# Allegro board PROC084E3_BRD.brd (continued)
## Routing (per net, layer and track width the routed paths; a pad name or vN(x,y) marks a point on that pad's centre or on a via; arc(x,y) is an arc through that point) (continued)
PRG1_RGMII1_RD3_R: length 6.3
  BOTTOM w0.173: R197.2 63.47,68.41 62.87,69.01 62.87,69.57 61.46,70.98 61.46,72.84 61.23,73.08 U30.36
PRG1_RGMII1_REF_CLK: length 30.8
  TOP w0.173: v1(57.15,83.11) 57.15,81.83 60.58,78.4 65.53,78.4 75.87,68.06 v1(78.51,68.06)
  BOTTOM w0.173: v1(57.15,83.11) 57.15,81.6 R186.1 ; R208.2 v1(78.51,68.06)
PRG1_RGMII1_RESET#: length 21.3
  TOP w0.173: v1(52.66,62.06) 53.69,63.08 58.94,63.08 60.53,64.67 60.53,69.86 59.97,70.42 56.97,70.42 v1(56.66,70.73)
  BOTTOM w0.173: U33.4 v1(52.66,62.06) ; U30.43 57.16,71.23 v1(56.66,70.73)
PRG1_RGMII1_RX_CTL: length 64.6
  L06_SIG2 w0.102: v1(71.91,118.84) 72.8,118.84 73.74,117.9 73.74,116.39 75.38,114.76 75.38,106.39 74.32,105.33 74.32,85.1 67.47,78.25 67.47,77.69 67.47,77.14 66.07,75.74 66.07,75.35 64.44,73.73 v1(64.44,66.93)
  BOTTOM w0.173: R342.2 v1(71.91,118.84) ; v1(64.44,66.93) 63.44,65.93 60.79,65.93 60.56,66.16 R200.1
PRG1_RGMII1_RX_CTL_R: length 7.8
  BOTTOM w0.173: U30.38 59.66,71.15 60.99,69.83 R47.1 59.58,69.22 R201.2 60.15,68.63 60.15,67.52 59.76,67.14 R200.2
PRG1_RGMII1_RXC: length 64.8
  L06_SIG2 w0.102: v1(66.52,75.44) 66.93,75.44 67.7,76.21 67.7,77.78 67.7,78.16 74.93,85.39 74.93,92.78 75.66,93.51 75.66,94.59 75.56,94.7 74.91,94.7 74.81,94.8 74.81,95.2 74.91,95.31 75.56,95.31 75.66,95.41 75.66,95.81 75.56,95.91 74.91,95.91 74.81,96.02 74.81,96.42 74.91,96.52 75.56,96.52 75.66,96.63 75.66,97.35 75.56,97.45 74.91,97.45 74.76,97.59 74.76,97.92 74.91,98.06 75.56,98.06 75.66,98.16 75.66,98.57 75.56,98.67 74.91,98.67 74.81,98.77 74.81,99.18 74.91,99.28 75.56,99.28 75.66,99.38 75.66,99.79 75.56,99.89 74.91,99.89 74.81,99.99 74.81,100.4 74.91,100.5 75.56,100.5 75.66,100.6 75.66,101 75.56,101.11 74.91,101.11 74.81,101.21 74.81,101.61 74.91,101.72 75.56,101.72 75.66,101.82 75.66,102.22 75.56,102.33 74.91,102.33 74.81,102.43 74.81,102.83 74.91,102.94 75.56,102.94 75.66,103.04 75.66,103.44 75.56,103.54 74.91,103.54 74.81,103.65 74.81,104.05 74.91,104.15 75.56,104.15 75.66,104.26 75.66,104.66 75.56,104.76 74.91,104.76 74.81,104.87 74.81,105.27 74.91,105.37 75.56,105.37 75.66,105.48 75.66,115 74.21,116.45 74.21,118.28 74.31,118.38 74.69,118.38 74.89,118.18 v1(74.89,116.76)
  BOTTOM w0.173: v1(74.89,116.76) R343.2 ; R191.1 v1(66.52,75.44)
PRG1_RGMII1_RXC_R: length 4.9
  BOTTOM w0.173: R191.2 65.04,74.86 61.62,74.86 61.4,75.08 U30.32
PRG1_RGMII1_TD0: length 49.2
  L06_SIG2 w0.102: v1(71.95,116.29) 73.35,116.29 74.27,115.36 74.27,111.55 73.94,111.21 73.94,110.62 73.24,109.92 71.13,109.92 69.72,108.51 69.72,92.4 69.82,92.3 70.61,92.3 70.71,92.2 70.71,91.79 70.61,91.69 69.82,91.69 69.72,91.59 69.72,91.18 69.82,91.08 70.61,91.08 70.71,90.98 70.71,90.58 70.61,90.47 69.82,90.47 69.72,90.37 69.72,83.12 65.62,79.01 v1(65.28,79.01)
  BOTTOM w0.173: R189.1 v1(65.28,79.01) ; R344.2 v1(71.95,116.29)
PRG1_RGMII1_TD0_R: length 3.7
  BOTTOM w0.173: R189.2 62.94,78.43 62.94,77.94 62.08,77.08 U30.28
PRG1_RGMII1_TD1: length 49.2
  L06_SIG2 w0.102: v1(73.75,114.55) 74.03,114.27 74.03,112.63 73.33,111.93 69.68,111.93 68.83,111.08 68.83,85.94 68.72,85.83 68,85.83 67.9,85.93 67.9,88.52 67.8,88.62 67.16,88.62 67.06,88.52 67.06,81.45 65.76,80.15 v1(65.28,80.15)
  BOTTOM w0.173: v1(73.75,114.55) 74.67,114.55 74.88,114.77 R345.2 ; R188.1 v1(65.28,80.15)
PRG1_RGMII1_TD1_R: length 4.3
  BOTTOM w0.173: U30.27 62.04,77.58 62.6,78.13 62.6,79.23 R188.2
PRG1_RGMII1_TD2: length 49.4
  L06_SIG2 w0.102: v1(65.28,81.29) 65.4,81.29 65.94,81.83 65.94,87.46 65.61,87.79 64.51,87.79 64.11,88.19 64.11,91.59 64.27,91.76 64.83,91.76 65,91.59 65,89.42 65.12,89.3 65.74,89.3 65.94,89.49 65.94,91.49 66.11,91.66 66.7,91.66 66.87,91.49 66.87,90.37 67.18,90.06 68.29,90.06 68.61,90.37 68.61,111.65 70.38,113.43 v1(71.92,113.43)
  BOTTOM w0.173: R346.2 72.74,113.43 v1(71.92,113.43) ; R187.1 v1(65.28,81.29)
PRG1_RGMII1_TD2_R: length 4.9
  BOTTOM w0.173: U30.26 61.86,78.08 62.25,78.46 62.25,80.03 R187.2
PRG1_RGMII1_TD3: length 49.1
  L06_SIG2 w0.102: v1(65.28,82.44) 64.8,81.96 64.8,79.99 65.09,79.69 65.65,79.69 67.54,81.58 67.54,85.35 67.65,85.45 68.24,85.45 68.35,85.35 68.35,83.09 68.47,82.96 68.88,82.96 69.06,83.15 69.06,110.92 69.81,111.67 v1(73.71,111.67)
  BOTTOM w0.173: R347.2 74.6,112.19 74.07,111.67 v1(73.71,111.67) ; R183.1 v1(65.28,82.44)
PRG1_RGMII1_TD3_R: length 5.3
  BOTTOM w0.173: U30.25 61.49,78.58 61.9,78.99 61.9,80.82 R183.2
PRG1_RGMII1_TX_CTL: length 49.4
  L06_SIG2 w0.102: v1(62.18,67.54) 63.09,68.45 63.09,77.48 65.07,79.47 65.75,79.47 69.49,83.21 69.49,108.86 71.14,110.5 v1(72.13,110.5)
  BOTTOM w0.173: v1(72.13,110.5) 72.74,110.5 R348.2 ; R199.1 62.18,68.19 v1(62.18,67.54)
PRG1_RGMII1_TX_CTL_R: length 3.9
  BOTTOM w0.173: R199.2 62.13,69.63 60.16,71.59 U30.37
PRG1_RGMII1_TXC: length 49.3
  L06_SIG2 w0.102: v1(65.28,77.87) 65.66,78.25 65.66,78.73 71.6,84.67 71.6,85.51 71.5,85.61 70.37,85.61 70.27,85.71 70.27,86.12 70.37,86.22 71.5,86.22 71.6,86.32 71.6,86.73 71.5,86.83 70.37,86.83 70.27,86.93 70.27,87.34 70.37,87.44 71.5,87.44 71.6,87.54 71.6,87.95 71.5,88.05 70.37,88.05 70.27,88.15 70.27,88.55 70.37,88.66 71.5,88.66 71.6,88.76 71.6,89.16 71.5,89.27 70.37,89.27 70.27,89.37 70.27,89.77 70.37,89.88 71.5,89.88 71.6,89.98 71.6,91.94 69.95,93.59 69.95,107.52 71.13,108.7 73.86,108.7 v1(73.86,108.69)
  BOTTOM w0.173: R190.1 v1(65.28,77.87) ; v1(73.86,108.69) 74.14,108.97 74.15,108.97 74.4,109.22 R349.2
PRG1_RGMII1_TXC_R: length 3.1
  BOTTOM w0.173: R190.2 62.3,76.65 60.98,76.65 U30.29
PRG1_RGMII1_XIN: length 2.3
  BOTTOM w0.173: U30.15 55.66,81.1 R184.2
PRG1_RGMII1_XOUT: length 2.2
  BOTTOM w0.173: R185.2 55.16,81.14 U30.14
PRG1_RGMII2_100MBPS: length 18.5
  TOP w0.132: J20.B13 9.84,74.69 8.42,74.69
  TOP w0.173: Q4.3 10.41,67.05 R49.2 10.14,67.72 9.55,68.32 7.14,68.32 4.95,70.5 4.95,74.11 5.53,74.69 8.42,74.69
PRG1_RGMII2_1000MBPS: length 10.7
  TOP w0.173: J20.B14 10.9,73.67 16.82,67.75 16.82,67.7 17.2,67.32 R51.2 17.53,67.05 Q6.3
PRG1_RGMII2_ACT_LED: length 9.4
  TOP w0.173: J20.B11 10.85,80.08 12.45,81.68 12.45,84.42 14.86,86.83 Q2.3
PRG1_RGMII2_CLK_OUT: length 7.7
  TOP w0.173: U3.18 v1(38.62,86.51)
  BOTTOM w0.173: TP11.1 35.82,83.71 v1(38.62,86.51)
PRG1_RGMII2_D0_N: length 32.4
  TOP w0.102: J20.B2 13.84,78.88 13.84,79.82 14.15,80.13 14.15,81.99 15.18,83.02 22.75,83.02 24.3,84.57 24.3,91 24.84,91.54 34.6,91.54 34.72,91.43 U3.2
PRG1_RGMII2_D0_P: length 32.5
  TOP w0.102: J20.B1 13.67,80.02 13.88,80.24 13.88,82.1 15.07,83.29 22.64,83.29 24.03,84.68 24.03,91.11 24.73,91.81 34.6,91.81 34.72,91.93 U3.1
PRG1_RGMII2_D1_N: length 28.8
  TOP w0.102: U3.5 34.72,89.93 34.6,90.04 26.14,90.04 25.59,89.49 25.59,83.69 24.27,82.37 17.23,82.37 16.69,81.83 16.69,80.15 16.41,79.87 16.41,78.85 J20.B4
PRG1_RGMII2_D1_P: length 28.8
  TOP w0.102: J20.B3 16.18,80.02 16.42,80.26 16.42,81.94 17.12,82.64 24.16,82.64 25.32,83.8 25.32,89.6 26.03,90.31 34.6,90.31 34.72,90.43 U3.4
PRG1_RGMII2_D2_N: length 25.2
  TOP w0.102: J20.B6 18.95,78.85 18.95,79.87 19.23,80.15 19.23,81.29 19.65,81.71 26.47,81.71 27.41,82.66 27.41,88.23 27.72,88.54 34.6,88.54 34.72,88.43 U3.8
PRG1_RGMII2_D2_P: length 25.2
  TOP w0.102: U3.7 34.72,88.93 34.6,88.81 27.61,88.81 27.14,88.35 27.14,82.77 26.36,81.98 19.54,81.98 18.96,81.4 18.96,80.26 18.72,80.02 J20.B5
PRG1_RGMII2_D3_N: length 21.2
  TOP w0.102: J20.B8 21.49,78.85 21.49,79.87 21.77,80.15 21.77,80.87 21.99,81.09 29.11,81.09 29.75,81.73 29.75,86.41 30.38,87.04 34.6,87.04 34.72,86.93 U3.11
PRG1_RGMII2_D3_P: length 21.3
  TOP w0.102: J20.B7 21.26,80.02 21.5,80.26 21.5,80.98 21.88,81.36 29,81.36 29.48,81.84 29.48,86.52 30.27,87.31 34.6,87.31 34.72,87.43 U3.10
PRG1_RGMII2_GPIO0_100: length 61.7
  TOP w0.173: R14.2 v1(39.88,95.09) 40.78,94.19 40.78,93.29 40.62,93.13 U3.39 ; Q4.1 v1(9.46,64.42)
  L03_SIG1 w0.102: v1(39.88,95.09) 39.37,94.58 38.46,94.58 38.31,94.73 37.93,94.73 36.58,93.38 36.58,73.1 27.09,63.62 16.61,63.62 14.86,65.37 10.41,65.37 v1(9.46,64.42)
  BOTTOM w0.173: v1(39.88,95.09) R14.2
PRG1_RGMII2_GPIO1: length 4.9
  TOP w0.173: R13.2 v1(38.73,95.09) 39.16,95.09 40.4,93.85 40.4,93.44 40.12,93.16 U3.40
  BOTTOM w0.173: v1(38.73,95.09) R13.2
PRG1_RGMII2_LED0: length 4.4
  TOP w0.173: R10.2 v1(35.31,95.09) 36.62,93.77 U3.47
  BOTTOM w0.173: v1(35.31,95.09) R10.2
PRG1_RGMII2_LED1_1000: length 49.9
  TOP w0.173: U3.46 37.12,94.41 v1(36.45,95.09) R11.2 ; Q6.1 v1(16.58,64.42)
  L03_SIG1 w0.102: v1(36.45,95.09) 36.35,94.99 36.35,74.61 25.68,63.95 17.05,63.95 v1(16.58,64.42)
  BOTTOM w0.173: v1(36.45,95.09) R11.2
PRG1_RGMII2_LED2_ACT: length 28.7
  TOP w0.173: U3.45 37.59,92.71 v1(37.59,95.09) R12.2 ; Q2.1 v1(15.81,90.73)
  L03_SIG1 w0.102: v1(37.59,95.09) 37.11,95.57 35,95.57 31.14,91.71 16.79,91.71 v1(15.81,90.73)
  BOTTOM w0.173: v1(37.59,95.09) R12.2
PRG1_RGMII2_RBIAS: length 2.3
  TOP w0.173: U3.12 v1(34.29,86.43)
  BOTTOM w0.173: R182.2 34.9,86.52 34.81,86.43 v1(34.29,86.43)
PRG1_RGMII2_RD0: length 64.9
  TOP w0.173: J1.39 v1(83.77,102.01) ; v1(48.65,91.69) 48.52,91.69 48.49,91.72 R24.1
  L03_SIG1 w0.102: v1(48.65,91.69) 48.05,91.69 47.81,91.45 47.81,90.64 49.77,88.67 58.63,88.67 59.81,87.48 60.08,87.48 60.18,87.59 60.18,88.69 60.28,88.79 60.69,88.79 60.79,88.69 60.79,87.59 60.89,87.48 61.3,87.48 61.4,87.59 61.4,88.69 61.5,88.79 61.84,88.79 61.94,88.69 61.94,87.6 62.05,87.48 71.25,87.48 76.25,92.48 76.25,95.7 76.35,95.8 76.63,95.8 76.73,95.7 76.73,91.94 76.83,91.83 77.06,91.83 77.22,91.99 77.22,100.78 77.49,101.05 78.88,101.05 79.15,100.78 81.49,100.78 81.83,101.12 83.36,101.12 83.51,101.27 83.51,101.49 83.77,101.75 v1(83.77,102.01)
PRG1_RGMII2_RD0_R: length 6.4
  TOP w0.173: R24.2 46.71,91.45 45.56,91.45 R180.2 44.98,91.99 44.97,91.99 R181.1 44.77,90.49 42.44,90.49 U3.33
PRG1_RGMII2_RD1: length 64.9
  TOP w0.173: R23.1 46.28,93.17 46.51,93.4 47.33,93.4 v1(47.88,92.85) ; J1.43 v1(84.01,103.01)
  L03_SIG1 w0.102: v1(47.88,92.85) 48.14,92.85 49.11,91.88 49.11,90.77 50.73,89.15 62.65,89.15 63.99,87.81 64.38,87.81 64.48,87.91 64.48,88.81 64.58,88.91 64.99,88.91 65.09,88.81 65.09,87.91 65.19,87.81 65.6,87.81 65.7,87.91 65.7,88.81 65.8,88.91 66.21,88.91 66.31,88.81 66.31,87.91 66.41,87.81 66.82,87.81 66.92,87.91 66.92,88.81 67.02,88.91 67.43,88.91 67.53,88.81 67.53,87.91 67.63,87.81 70.28,87.81 75.87,93.4 75.87,99.18 75.97,99.28 76.25,99.28 76.35,99.18 76.35,96.31 76.45,96.2 76.73,96.2 76.83,96.31 76.83,100.87 77.46,101.49 78.88,101.49 79.48,102.09 82.12,102.09 82.29,101.92 82.66,101.92 82.93,102.19 82.93,102.3 83.64,103.01 v1(84.01,103.01)
PRG1_RGMII2_RD1_R: length 4.4
  TOP w0.173: U3.34 43.86,90.93 44.26,91.32 44.26,92.8 44.63,93.17 R23.2
PRG1_RGMII2_RD2: length 64.7
  TOP w0.173: J1.41 83.16,102.51 83.06,102.41 82.51,102.41 82.48,102.38 v1(82.48,102.38) ; R22.1 48.46,94.57 v1(47.88,93.99)
  L03_SIG1 w0.102: v1(47.88,93.99) 48.79,93.99 49.47,93.31 49.47,91.45 51.34,89.58 61.81,89.58 61.91,89.68 61.91,91.07 62.01,91.18 62.42,91.18 62.52,91.07 62.52,89.68 62.62,89.58 63.03,89.58 63.13,89.68 63.13,91.07 63.23,91.18 63.64,91.18 63.74,91.07 63.74,89.68 63.84,89.58 65.74,89.58 66.95,90.79 69.36,90.79 69.46,90.69 69.46,89.79 69.56,89.69 69.84,89.69 69.94,89.79 69.94,90.69 70.04,90.79 72.94,90.79 74.63,92.47 74.63,95.85 74.73,95.95 75.01,95.95 75.11,95.85 75.11,93.56 75.21,93.45 75.49,93.45 75.59,93.56 75.59,101.35 76.64,102.41 78.05,102.41 78.37,102.09 78.75,102.09 79.06,102.41 82.45,102.41 v1(82.48,102.38)
PRG1_RGMII2_RD2_R: length 9.2
  TOP w0.173: U3.35 43.44,91.43 43.68,91.67 43.68,93.57 44.43,94.32 R179.2 44.98,95.68 ; R22.2 47.11,95.15 46.38,95.15 46.33,95.1 45.56,95.1 45.51,95.15 45.5,95.15 44.98,95.68 ; R178.1 44.98,95.68
PRG1_RGMII2_RD3: length 65.3
  TOP w0.173: R19.1 45.97,96.93 46.68,96.22 v1(46.68,95.65) ; J1.45 83.36,103.51 v1(82.86,103.01)
  L03_SIG1 w0.102: v1(46.68,95.65) 46.95,95.38 46.95,95.38 47.07,95.26 54.49,95.26 54.59,95.16 54.59,93.09 54.69,92.99 55.1,92.99 55.2,93.09 55.2,95.16 55.3,95.26 55.71,95.26 55.81,95.16 55.81,93.09 55.91,92.99 56.32,92.99 56.42,93.09 56.42,95.16 56.52,95.26 63.55,95.26 67.64,91.18 73,91.18 74.35,92.52 74.35,97.8 74.45,97.9 74.73,97.9 74.83,97.8 74.83,96.48 74.93,96.38 75.21,96.38 75.31,96.48 75.31,98.28 75.21,98.39 74.73,98.39 74.63,98.49 74.63,101.88 75.75,103.01 v1(82.86,103.01)
PRG1_RGMII2_RD3_R: length 6.4
  TOP w0.173: R19.2 44.99,97.06 44.56,96.63 44.56,96.54 44.4,96.38 44.4,95.27 43.12,93.99 43.12,92.36 42.69,91.93 U3.36
PRG1_RGMII2_REF_CLK: length 38.5
  TOP w0.173: R32.1 39.34,82.67 44.15,82.67 44.35,82.46 44.35,82.13 44.7,81.78 56.46,81.78 60.64,77.6 62.46,77.6 64.4,75.65 64.4,72.07 66.33,70.14 v1(66.33,68.11)
  BOTTOM w0.173: R207.2 v1(66.33,68.11)
PRG1_RGMII2_RESET#: length 12.9
  TOP w0.173: U3.43 38.62,93.77 v1(38.12,94.27) ; U2.4 v1(29.52,97.69)
  BOTTOM w0.173: v1(38.12,94.27) 35.15,94.27 31.74,97.69 v1(29.52,97.69)
PRG1_RGMII2_RX_CTL: length 64.9
  TOP w0.173: J1.47 83.36,104.01 v1(83.36,104.01) ; R16.1 v1(41.91,98.65)
  L03_SIG1 w0.102: v1(83.36,104.01) 83.35,104.02 83.35,104.03 82.86,104.51 73.92,104.51 73.1,103.69 73.1,92.71 72.91,92.52 68.53,92.52 63.59,97.46 50.69,97.46 45.96,102.19 41.7,102.19 40.65,101.14 40.65,99.16 41.16,98.65 v1(41.91,98.65)
PRG1_RGMII2_RX_CTL_R: length 7.6
  TOP w0.173: U3.38 41.12,94.08 42.45,95.41 R170.1 41.03,95.8 R15.2 41.11,95.79 41.6,96.28 41.6,97.16 41.09,97.67 R16.2
PRG1_RGMII2_RXC: length 60.1
  TOP w0.173: v1(47.51,89.39) 48,89.88 R25.1 ; v1(82.62,104.04) 83.09,104.51 J1.49
  L03_SIG1 w0.102: v1(47.51,89.39) 47.51,89.79 46.08,91.23 46.08,95.92 46.34,96.19 48.19,96.19 48.83,95.54 63.88,95.54 68.02,91.4 72.91,91.4 73.89,92.38 73.89,101.47 76.43,104.01 82.59,104.01 v1(82.62,104.04)
PRG1_RGMII2_RXC_R: length 4.8
  TOP w0.173: R25.2 46.53,90.29 46.34,90.11 43.52,90.11 43.49,90.14 43.08,90.14 42.86,89.93 U3.32
PRG1_RGMII2_TD0: length 72.1
  TOP w0.173: J1.14 93.08,95.51 v1(93.58,95.01) ; R29.1 v1(46.74,85.99)
  L03_SIG1 w0.102: v1(46.74,85.99) 47.32,85.99 47.5,85.82 47.5,84.02 47.6,83.91 52.35,83.91 52.53,83.73 52.53,83.46 52.35,83.28 47.35,83.28 47.24,83.17 47.24,82.9 47.35,82.79 55,82.79 57.08,84.88 62.26,84.88 63.25,85.87 72.45,85.87 79.79,93.2 80.19,93.6 80.19,95.33 80.46,95.6 82.56,97.7 88.87,97.7 92.03,94.55 93.12,94.55 v1(93.58,95.01)
PRG1_RGMII2_TD0_R: length 3.7
  TOP w0.173: R29.2 44.4,86.57 44.4,87.06 43.53,87.93 U3.28
PRG1_RGMII2_TD1: length 72
  TOP w0.173: J1.18 93.08,96.51 v1(93.58,96.01) ; R30.1 v1(46.74,84.85)
  L03_SIG1 w0.102: v1(46.74,84.85) 46.18,84.85 45.75,85.29 45.75,87.72 45.85,87.82 59.05,87.82 59.16,87.72 59.16,87.44 59.05,87.34 54.43,87.34 54.33,87.24 54.33,86.96 54.43,86.86 72.48,86.86 79.5,93.88 79.5,95.72 82.27,98.49 90.27,98.49 92.23,96.53 93.05,96.53 v1(93.58,96.01)
PRG1_RGMII2_TD1_R: length 4.3
  TOP w0.173: U3.27 43.5,87.43 44.05,86.87 44.05,85.77 R30.2
PRG1_RGMII2_TD2: length 72.6
  TOP w0.173: R31.1 v1(46.74,83.71) ; J1.16 v1(92.43,96.01)
  L03_SIG1 w0.102: v1(92.43,96.01) 90.18,98.26 82.37,98.26 79.73,95.63 79.73,93.79 79.6,93.66 72.52,86.58 48.63,86.58 48.46,86.75 48.46,86.89 48.63,87.06 53.59,87.06 53.7,87.16 53.7,87.44 53.54,87.59 46.33,87.59 46.05,87.31 46.05,86.02 46.71,85.36 47.02,85.36 47.19,85.18 47.19,84.63 46.92,84.36 45.96,84.36 45.82,84.22 45.82,83.81 45.93,83.71 v1(46.74,83.71)
PRG1_RGMII2_TD2_R: length 4.9
  TOP w0.173: U3.26 43.32,86.93 43.71,86.54 43.71,84.98 R31.2
PRG1_RGMII2_TD3: length 72.3
  TOP w0.173: J1.10 92.92,94.51 v1(93.58,93.85) ; R35.1 v1(46.74,82.56)
  L03_SIG1 w0.102: v1(93.58,93.85) 93.31,94.12 93.31,94.15 93.13,94.32 91.55,94.32 88.39,97.47 82.65,97.47 80.55,95.37 80.42,95.24 80.42,93.51 79.88,92.97 72.52,85.61 65.11,85.61 65.01,85.51 65.01,85.23 65.11,85.13 71.47,85.13 71.57,85.03 71.57,84.75 71.47,84.65 57.18,84.65 55.09,82.56 v1(46.74,82.56)
PRG1_RGMII2_TD3_R: length 5.3
  TOP w0.173: U3.25 42.95,86.43 43.36,86.01 43.36,84.18 R35.2
PRG1_RGMII2_TX_CTL: length 72.7
  TOP w0.173: v1(44.18,97.44) 43.81,97.44 43.59,97.22 R17.1 ; v1(92.43,93.85) 92.43,93.88 92.31,94.01 J1.8
  L03_SIG1 w0.102: v1(92.43,93.85) 91.22,93.85 88.54,96.53 82.04,96.53 80.64,95.14 80.64,93.41 79.98,92.74 71.65,84.42 57.43,84.42 55.09,82.08 46.57,82.08 45.24,83.41 45.24,95.53 44.91,95.86 44.91,96.71 v1(44.18,97.44)
PRG1_RGMII2_TX_CTL_R: length 4
  TOP w0.173: R17.2 43.55,95.8 41.62,93.87 U3.37
PRG1_RGMII2_TXC: length 72.3
  TOP w0.173: R28.1 v1(46.74,87.14) ; J1.12 v1(92.43,95.01)
  L03_SIG1 w0.102: v1(92.43,95.01) 89.41,98.03 82.46,98.03 79.96,95.53 79.96,93.69 79.69,93.43 72.44,86.17 63.17,86.17 62.48,85.49 49.07,85.49 48.97,85.38 48.97,85.1 49.07,85 56.22,85 56.33,84.9 56.33,84.65 56.22,84.55 48.16,84.55 48.01,84.7 48.01,85.87 v1(46.74,87.14)
PRG1_RGMII2_TXC_R: length 3.1
  TOP w0.173: R28.2 43.76,88.36 42.44,88.36 U3.29
PRG1_RGMII2_XIN: length 2.3
  TOP w0.173: R32.2 37.12,83.91 U3.15
PRG1_RGMII2_XOUT: length 2.2
  TOP w0.173: R33.2 36.62,83.86 U3.14
PRG1_RGMII_INT#: length 116.7
  TOP w0.173: v1(76.53,44.49) 80.09,44.49 82.73,47.13 J2.17 ; R41.1 56.2,70.96 56.66,71.43 v1(56.66,71.49) 57.32,70.84 61.99,70.84 65.41,67.43 75.71,67.43 v1(80.74,62.4) ; U3.44 v1(38.12,93.51)
  L03_SIG1 w0.102: v1(56.66,71.49) 54.76,71.49 52.25,68.98 52.25,66.48 51.13,65.37 50.9,65.37 50.26,64.73 50.26,61.89 47.81,59.44 46.55,59.44 45.31,60.68 45.31,62.47 36.88,70.91 36.88,86.02 38.12,87.26 v1(38.12,93.51)
  L06_SIG2 w0.102: v1(80.74,62.4) 80.06,61.72 80.06,49.06 76.53,45.53 v1(76.53,44.49)
  BOTTOM w0.173: U30.44 v1(56.66,71.49)
PRG1_UART0_CTSN: length 97.4
  TOP w0.173: R285.1 v1(98.3,102.05)
  L03_SIG1 w0.102: v1(67.99,179.36) 67.99,177.16 86.74,158.41 86.74,132.37 98.3,120.82 v1(98.3,102.05)
  BOTTOM w0.173: R284.1 v1(67.99,179.36)
PROFI_D1: length 8
  BOTTOM w0.173: T1.4 32.77,116.49 32.94,116.31 32.94,112.56 31.68,111.3 U26.1
PROFI_D2: length 21.9
  BOTTOM w0.173: T1.1 31.49,123.72 31.66,123.89 35.01,123.89 35.36,123.54 35.36,112.69 32.7,110.03 U26.2
PROFI_DE/RE#: length 5.5
  BOTTOM w0.173: U26.6 R162.2 R163.1 U26.7
PROFI_EN#: length 2
  TOP w0.173: U1.4 19.3,112.29 R5.1
PROFI_PG: length 3.5
  TOP w0.173: v1(16.75,111.38) R4.1 16.76,112.16 U1.2
  BOTTOM w0.173: R4.1 v1(16.75,111.38)
PROFI_UART0_RTSN: length 25.8
  L06_SIG2 w0.102: v1(48.96,118.07) 49.45,117.58 49.45,115.2 45.8,111.55 39.07,111.55 34.01,106.49 34.01,105.44 v1(34.5,104.95)
  BOTTOM w0.173: R162.1 v1(34.5,104.95) ; U22.4 v1(48.96,118.07)
PROFI_UART0_RXD: length 22.5
  L06_SIG2 w0.102: v1(49.98,115.47) 49.98,115.41 41.24,106.67 34.95,106.67 v1(34.5,106.22)
  BOTTOM w0.173: v1(49.98,115.47) 49.33,116.12 U22.7 ; R161.1 v1(34.5,106.22)
PROFI_UART0_TXD: length 21.2
  L06_SIG2 w0.102: v1(34.5,102.41) 34.05,102.41 33.77,102.69 33.77,112.04 37.85,116.12 v1(39.94,116.12)
  BOTTOM w0.173: v1(39.94,116.12) 40.59,115.47 U22.9 ; R165.1 v1(34.5,102.41)
PROFI_UART_RX: length 2.1
  BOTTOM w0.173: U26.5 R161.2
PROFI_UART_SEL: length 146.7
  TOP w0.173: v1(65.02,119.34) 64.44,119.93 50.54,119.93 v1(49.98,119.37) ; U42.1 69.67,41.69 69.38,41.99 67,41.99 v1(64.55,44.43)
  L03_SIG1 w0.102: v1(78.43,66.39) 78.22,66.6 68.61,66.6 64.41,62.41 64.41,44.58 v1(64.55,44.43)
  L06_SIG2 w0.102: v1(65.02,119.34) 65.02,123.2 66.74,124.92 74.7,124.92 79.46,120.16 79.46,116.58 78.4,115.53 78.4,112.29 v1(81.82,108.88)
  BOTTOM w0.173: v1(65.02,119.34) 64.37,119.99 U23.1 60.82,119.99 60.56,120.25 R154.1 ; U22.1 49.33,120.02 v1(49.98,119.37) ; v1(78.43,66.39) 78.61,66.39 79.72,67.5 79.72,74.47 80.43,75.19 80.43,96.88 81.15,97.59 81.15,103.96 82.16,104.98 82.16,108.7 81.99,108.88 v1(81.82,108.88) 81.35,108.88 79.73,110.5 R300.2
PROFI_UART_TX: length 2.1
  BOTTOM w0.173: U26.8 R165.2
PROFIB_GND: length 10.7
  TOP w0.254: v1(17.6,111.42) 18.18,112 R5.2 18.03,112.29 U1.3 ; C8.1 v1(9.09,116.86)
  BOTTOM w0.254: U26.9 v1(20.03,102.41) ; U26.14 v1(20.03,108.76) ; C113.2 19.92,110.14 v1(20.03,110.03) U26.15 ; U26.11 v1(20.03,104.95)
  vias: v1(17.45,124.96) v1(18.64,124.94) v1(18.67,100.4) v1(19.91,100.4) v1(20.14,124.91) v1(21.16,100.4) v1(21.37,125.81) v1(21.36,124.94)
PROFIBUS_DATA_N: length 18
  BOTTOM w0.102: 16.09,109.62 D6.1 ; 16.09,109.62 15.98,109.51 15.54,109.51 13.59,111.47 9.93,111.47 9.04,110.58 9.04,109.4 J18.8 ; 16.09,109.62 16.19,109.51 17.22,109.51 19.68,107.06 20.3,107.06 20.74,107.49 U26.13
PROFIBUS_DATA_P: length 18
  BOTTOM w0.102: 16.09,109.01 16.19,109.11 17.05,109.11 19.51,106.65 20.31,106.65 20.74,106.22 U26.12 ; 16.09,109.01 15.98,109.11 15.38,109.11 13.42,111.06 10.1,111.06 9.45,110.41 9.45,109.21 9.58,109.08 10.2,109.08 J18.3 ; 16.09,109.01 D6.2
RESETSTATZ: length 2.7
  TOP w0.173: J2.30 v1(90.07,50.13)
  BOTTOM w0.173: v1(90.07,50.13) 90.04,50.15 TP29.1
RGMII_CLK_BUF_EN: length 2.1
  BOTTOM w0.173: R194.1 68.08,71.89 U31.8
RGMII_REF_CLOCK: length 69.4
  TOP w0.173: J1.106 90.24,123.51 90.07,123.34 90.07,120.24 v1(89.84,120)
  L06_SIG2 w0.102: v1(76.84,71.89) 78.65,71.89 80.75,73.98 80.75,83.25 81.7,84.2 87.31,89.81 87.31,90.98 86.26,92.03 86.26,100.67 86.91,101.32 86.91,104.25 86.26,104.9 86.26,108.04 82.94,111.35 82.94,112.48 81.66,113.77 81.66,116.95 82.16,117.45 84.59,117.45 86.26,119.12 88.95,119.12 v1(89.84,120)
  BOTTOM w0.173: U31.1 v1(76.84,71.89)
RMII8_50MHZ_REFCLK: length 65.1
  L03_SIG1 w0.102: v1(39.98,18.19) 39.35,18.82 37.1,18.82 35.1,20.81 35.1,22.13 35.59,22.62 38.55,22.62 40.07,24.15 40.07,27.19 40.81,27.93 53.09,27.93 67.61,42.46 67.61,54.08 v1(67.2,54.5)
  BOTTOM w0.173: R268.1 40.32,17.85 v1(39.98,18.19) ; R225.1 67.03,54.95 67.2,54.78 v1(67.2,54.5)
RMII8_AVD33: length 4.4
  TOP w0.254: v1(30.54,26.14) C61.1
  BOTTOM w0.254: U40.14 32.61,26.11 C182.1 C61.1 v1(30.54,26.14)
RMII8_CRS_DV: length 75.3
  TOP w0.173: R96.1 v1(41.01,27.45) ; J2.64 v1(92.43,63.63)
  L03_SIG1 w0.102: v1(41.01,27.45) 53.34,27.45 69.29,43.4 69.29,50.21 78.81,59.73 83.69,59.73 87.6,63.63 v1(92.43,63.63)
  BOTTOM w0.173: U40.27 39.67,26.11 v1(41.01,27.45) R96.1
RMII8_LED0: length 41.1
  TOP w0.173: v1(33.31,29.86) R94.1 32.62,31.38 31.36,32.64 20.38,32.64 18.21,34.81 13.82,34.81 9.75,30.75 5.18,30.75 3.5,32.43 J23.12
  BOTTOM w0.173: R94.1 v1(33.31,29.86) 33.31,28.61 33.6,28.31 34.72,28.31 34.89,28.14 U40.17
RMII8_LED1: length 32.3
  TOP w0.173: v1(29.39,21.15) 26.82,21.15 20.87,15.19 Q13.1
  L06_SIG2 w0.102: v1(39.27,28.26) 35.71,28.26 29.39,21.94 v1(29.39,21.15)
  BOTTOM w0.173: v1(39.27,28.26) 38.53,28.26 38.39,28.12 U40.24
RMII8_MDI_RD_N: length 25.3
  BOTTOM w0.102: U40.9 33.5,23.61 33.38,23.72 32.9,23.72 32.75,23.58 32.75,22.76 32.44,22.45 31.96,22.45 31.86,22.35 31.86,22.17 31.76,22.07 R292.2 30.67,22.07 30.57,22.17 30.57,22.35 30.47,22.45 24.31,22.45 18.56,28.2 16.15,28.2 15.21,29.13 15.21,30.08 J23.8
RMII8_MDI_RD_P: length 25.3
  BOTTOM w0.102: U40.10 33.5,24.11 33.38,23.99 32.79,23.99 32.49,23.69 32.49,22.87 32.33,22.72 31.96,22.72 31.86,22.82 31.86,22.99 31.76,23.1 R291.2 30.67,23.1 30.57,22.99 30.57,22.82 30.47,22.72 24.42,22.72 18.67,28.46 16.26,28.46 15.48,29.24 15.48,29.91 15.58,30.01 16.56,30.01 J23.7
RMII8_MDI_TD_N: length 24.5
  BOTTOM w0.102: U40.11 33.5,24.61 33.38,24.72 29.47,24.72 29.37,24.62 29.37,24.44 29.27,24.34 R290.2 28.19,24.34 28.08,24.44 28.08,24.62 27.98,24.72 24.83,24.72 18.81,30.74 16.14,30.74 15.11,31.76 15.11,32.73 J23.10
RMII8_MDI_TD_P: length 24.5
  BOTTOM w0.102: J23.9 16.61,32.5 15.49,32.5 15.38,32.39 15.38,31.88 16.25,31 18.92,31 24.94,24.99 27.98,24.99 28.08,25.09 28.08,25.27 28.19,25.37 R289.2 29.27,25.37 29.37,25.27 29.37,25.09 29.47,24.99 33.38,24.99 33.5,25.11 U40.12
RMII8_MODE_XI50: length 4.6
  TOP w0.173: R95.1 v1(41.01,28.72)
  BOTTOM w0.173: U40.26 39.65,26.61 40.28,27.24 40.28,27.99 v1(41.01,28.72) R95.1
RMII8_PHY_INTN: length 78.4
  TOP w0.173: J2.56 v1(92.43,56.63)
  L03_SIG1 w0.102: v1(92.43,56.63) 92.02,56.63 84.27,48.88 70.54,48.88 70.21,48.55 70.21,43.17 52.91,25.87 42.98,25.87 38.63,21.53 35.99,21.53 v1(35.59,21.94)
  BOTTOM w0.173: U40.8 R269.1 34.93,21.28 v1(35.59,21.94)
RMII8_PHY_RESET: length 70.5
  TOP w0.173: v1(27.14,39.03) 29.96,41.85 41.45,41.85 53.16,53.56 76.66,53.56 81.04,57.94 81.04,58.52 83.44,60.92 83.44,63.06 84.01,63.63 J2.63
  BOTTOM w0.173: R248.1 v1(27.14,39.03)
RMII8_PHYAD0: length 8.9
  TOP w0.173: R98.1 v1(41.01,24.91)
  BOTTOM w0.173: TP21.1 43.72,26.62 43.53,26.43 43.53,24.58 43.22,24.27 41.83,24.27 41.7,24.41 R98.1 v1(41.01,24.91) 40.81,25.11 U40.29
RMII8_PHYAD1: length 7.9
  BOTTOM w0.173: R99.1 44.37,24.91 R263.2 44.37,23.21 44.21,23.05 41.83,23.05 41.7,23.18 R264.2 41.07,23.64 40.1,24.61 U40.30
RMII8_PHYAD2: length 7.7
  BOTTOM w0.173: U40.31 39.96,24.11 R266.2 41.7,21.99 41.94,21.75 44.18,21.75 ; 44.18,21.75 44.37,21.56 R100.1 ; 44.18,21.75 44.37,21.93 R265.2
RMII8_PHYAD3: length 5.1
  TOP w0.173: R101.1 v1(41.01,21.1)
  BOTTOM w0.173: R101.1 v1(41.01,21.1) 40.26,21.85 40.26,23.21 39.86,23.61 U40.32
RMII8_PHYAD4: length 6.9
  TOP w0.173: R102.1 v1(41.01,19.83)
  BOTTOM w0.173: R268.2 41.7,19.83 R102.1 v1(41.01,19.83) 39.56,21.28 38.92,21.28 38.39,21.81 U40.1
RMII8_RBIAS: length 2.1
  BOTTOM w0.173: U40.16 33.98,27.11 33.78,27.3 33.78,27.32 32.64,28.46 R259.1
RMII8_RX_ER: length 75.8
  TOP w0.173: v1(93.58,57.63) 93.08,57.13 J2.58 ; R97.1 v1(41.01,26.18)
  L03_SIG1 w0.102: v1(41.01,26.18) 52.87,26.18 69.9,43.21 69.9,48.78 70.23,49.11 84.18,49.11 91.89,56.83 91.89,57.77 92.27,58.16 93.05,58.16 v1(93.58,57.63)
  BOTTOM w0.173: U40.28 40.44,25.61 v1(41.01,26.18) R97.1
RMII8_RXD0: length 65.9
  TOP w0.173: v1(92.45,53.56) 92.38,53.63 J2.44
  L03_SIG1 w0.102: v1(92.45,53.56) 92.39,53.56 86.82,48 84.12,48 81.1,44.98 81.1,44.46 72.01,35.37 65.54,35.37 55.76,25.59 54.1,25.59 51.64,23.13 44.93,23.13 44.83,23.23 44.83,23.92 44.73,24.02 44.45,24.02 44.35,23.92 44.35,23.15 44.25,23.05 43.78,23.05 43.68,23.15 43.68,23.51 v1(43.55,23.64)
  BOTTOM w0.173: R264.1 v1(43.55,23.64)
RMII8_RXD1: length 66
  TOP w0.173: J2.48 v1(92.43,54.63)
  L03_SIG1 w0.102: v1(92.43,54.63) 92.91,54.15 92.91,53.23 92.63,52.94 92.1,52.94 86.79,47.64 84.21,47.64 81.43,44.87 81.43,44.41 72.11,35.09 65.58,35.09 55.8,25.31 54.15,25.31 51.66,22.82 44.09,22.82 43.64,22.37 v1(43.55,22.37)
  BOTTOM w0.173: R266.1 v1(43.55,22.37)
RMII8_SPEED_LED: length 8.8
  TOP w0.173: J23.13 6.35,20.16 6.35,19.22 9.42,16.14 Q13.3
RMII8_TX_EN: length 80.8
  TOP w0.173: v1(91.49,61.44) 91.49,61.49 92.43,62.43 92.43,62.93 92.23,63.13 J2.62
  L03_SIG1 w0.102: v1(91.49,61.44) 91.47,61.44 90.31,62.6 87.1,62.6 83.96,59.46 79,59.46 69.55,50.01 69.55,43.18 53.08,26.71 40.73,26.71 40.56,26.53 40.56,23.95 38.64,22.03 v1(37.39,22.03)
  BOTTOM w0.173: U40.3 v1(37.39,22.03)
RMII8_TXD0: length 75.5
  TOP w0.173: J2.60 v1(92.43,57.63)
  L03_SIG1 w0.102: v1(37.39,21.02) 39.36,21.02 43.38,25.03 52.46,25.03 63.43,36.01 71.78,36.01 80.34,44.57 80.34,45.23 83.77,48.66 84.66,48.66 92.13,56.12 92.76,56.12 93.04,56.4 93.04,57.34 92.75,57.63 v1(92.43,57.63)
  BOTTOM w0.173: v1(37.39,21.02) 36.89,21.52 U40.4
RMII8_TXD1: length 75.7
  TOP w0.173: J2.46 92.71,54.13 v1(93.21,54.62)
  L03_SIG1 w0.102: v1(93.21,54.62) 92.73,55.1 91.91,55.1 85.24,48.43 84.15,48.43 80.64,44.92 80.64,44.46 71.83,35.65 63.4,35.65 52.32,24.58 43.81,24.58 39.78,20.54 36.87,20.54 v1(36.39,21.02)
  BOTTOM w0.173: U40.5 v1(36.39,21.02)
RMII8_XI: length 8.3
  BOTTOM w0.173: U40.23 37.89,28.68 38.09,28.88 38.99,28.88 39.37,29.25 39.37,29.35 39.37,29.81 39.71,30.14 C178.2 39.71,30.18 39.37,30.52 39.37,32.65 39.69,32.98 Y5.2
RMII8_XO: length 7.8
  BOTTOM w0.173: U40.22 37.44,27.91 37.44,28.72 37.95,29.22 38.85,29.22 39.02,29.4 39.02,29.81 C179.2 38.65,30.21 38.96,30.52 38.96,32.63 38.62,32.98 Y5.1
SOC_I2C2_SCL: length 3.1
  TOP w0.173: v1(89.74,125.72) 90.45,125.01 J1.112
  BOTTOM w0.173: v1(89.74,125.72) 89.53,125.52 TP22.1
SOC_I2C2_SDA: length 4.6
  TOP w0.173: v1(93.76,126.33) 92.94,125.51 J1.114
  BOTTOM w0.173: TP23.1 94.46,127.03 v1(93.76,126.33)
SOC_PORZ_OUT: length 246
  TOP w0.173: v1(92.43,112.05) 92.85,112.05 92.98,112.19 R3.1 92.76,113.01 J1.64 ; v1(30.73,64.91) 27.08,64.91 26.41,64.24 U4.1 ; U2.1 27.63,96.9 27.8,97.08 v1(31.42,97.08)
  L03_SIG1 w0.102: v1(30.66,35.93) 44.81,35.93 v1(45.84,36.95) ; v1(30.73,64.91) 31.42,64.91 32.08,65.57 41.67,65.57 44.93,62.31 44.93,60.73 46.45,59.21 47.91,59.21 50.76,62.07 v1(50.76,64.51)
  L06_SIG2 w0.102: v1(30.66,35.93) 30.66,64.84 v1(30.73,64.91) 35.56,64.91 39.78,69.13 39.78,72.06 48.94,81.23 49.21,81.49 49.21,91.92 48.87,92.26 48.87,96.7 47.53,98.05 43.97,98.05 42.02,96.1 42.02,96.05 34.45,96.05 33.06,94.66 32.68,94.66 31.27,96.07 31.27,96.92 v1(31.42,97.08) 33.64,97.08 36.3,99.74 38.28,99.74 52.4,113.85 52.4,122.29 55.49,125.38 75.59,125.38 76.37,124.6 84.15,124.6 84.75,124 86.85,124 90.7,120.15 90.7,113.78 v1(92.43,112.05)
  BOTTOM w0.173: U33.1 v1(50.76,64.51) 50.37,64.91 TP33.1 ; v1(30.66,35.93) 29.74,35.02 26.42,35.02 26.19,35.24 U39.1 ; U38.1 v1(45.84,36.95)
SPI3_CLK: length 185.8
  TOP w0.173: R2.1 62.15,138.98 62.46,138.67 v1(65.58,138.67) ; v1(82.86,123.01) 83.36,123.51 J1.105
  L03_SIG1 w0.102: J24.24 63.69,11.7 84.94,11.7 92.86,19.62 92.86,32.43 94.61,34.18 94.61,51.68 96.22,53.28 96.22,120.08 93.8,122.49 92.2,122.49 91.24,121.53 82.66,121.53 82.38,121.81 82.38,122.53 v1(82.86,123.01) 82.86,125.99 70.18,138.67 v1(65.58,138.67)
SPI3_CS1: length 270.7
  TOP w0.173: v1(79.95,106.73) 80.17,106.51 J1.57
  L06_SIG2 w0.102: v1(79.95,106.73) 79.95,106.38 77.42,103.86 77.42,84.8 71.15,78.53 71.15,71.63 65.53,66.01 64,66.01 62.6,64.61 51.36,64.61 50.88,65.09 50.23,65.74 48.21,65.74 47.19,64.72 47.19,64.12 47.36,63.95 47.36,59.13 45.88,57.64 45.88,56.73 45.42,56.27 45.42,45.58 45.01,45.17 45.01,35.93 60.43,20.51 79.58,20.51 81.91,18.18 J24.3
  BOTTOM w0.173: J5.4 72.19,187.21 72.19,179.6 47.13,154.54 47.13,144.31 50.28,141.16 68.88,141.16 70.66,139.38 70.66,108.55 72.87,106.34 79.77,106.34 79.95,106.51 v1(79.95,106.73)
SPI3_CS2: length 128.1
  TOP w0.173: J1.59 80.98,107.01 80.83,107.16 v1(80.73,107.16)
  BOTTOM w0.173: v1(80.73,107.16) 80.73,106.35 80.21,105.83 72.53,105.83 70.32,108.05 70.32,139.03 68.72,140.63 50.15,140.63 46.79,144 46.79,154.9 69.75,177.87 69.75,187.31 J5.6
SPI3_D0: length 235.9
  TOP w0.173: v1(82.86,122.01) 83.36,122.51 J1.101
  L03_SIG1 w0.102: J24.26 59.91,12.37 61.62,10.66 85,10.66 93.44,19.1 93.44,32.22 95.1,33.87 95.1,50.51 96.72,52.13 96.72,121.08 94.83,122.98 91.64,122.98 91,122.34 83.69,122.34 83.36,122.01 v1(82.86,122.01) 82.86,122.3 83.41,122.85 83.41,156.15 64.17,175.39 64.17,183.56 62.15,185.57 62.15,187.33 J5.12
SPI3_D1: length 240.4
  TOP w0.173: J1.103 v1(84.01,123.01)
  L03_SIG1 w0.102: J5.14 62.36,190.08 64.16,190.08 64.62,189.63 64.62,175.52 84.09,156.05 84.09,128.35 85.22,127.22 85.22,124.25 84.01,123.04 v1(84.01,123.01) 84.41,123.01 84.72,122.7 90.92,122.7 91.43,123.2 94.92,123.2 96.95,121.18 96.95,51.85 95.5,50.41 95.5,33.57 93.67,31.73 93.67,19.01 85.09,10.43 59.49,10.43 57.91,12.01 J24.28
SPI6_CLK/PRG1_ECAP0_SYNC_OUT: length 113.6
  TOP w0.173: v1(93.58,101.01) 93.08,100.51 J1.34
  L06_SIG2 w0.102: J24.18 69.51,11.88 84.94,11.88 88.8,15.74 88.8,64.98 91.62,67.8 91.62,76.58 91.34,76.86 91.34,87.16 91.84,87.66 91.84,87.66 94.11,89.93 94.11,100.48 v1(93.58,101.01)
SPI6_CS1/PRG1_PWM3_TZ_IN: length 122.2
  TOP w0.173: R286.2 v1(94.63,98.39)
  L06_SIG2 w0.102: v1(94.63,98.39) 94.63,89.77 91.82,86.96 91.82,77.12 92.1,76.84 92.1,67.6 89.28,64.78 89.28,15.43 85.24,11.39 57.63,11.39 55.91,13.12 J24.30
SPI6_D0/PRG1_ECAP0_SYNC_IN: length 159.7
  TOP w0.173: v1(82.33,99.97) 82.33,100.24 82.6,100.51 J1.33
  L06_SIG2 w0.102: v1(82.33,99.97) 78.44,96.07 78.44,84.67 73.12,79.36 73.12,72.96 63.73,63.57 57.43,63.57 56.99,64 50.6,64 49.46,65.14 47.94,65.14 47.42,64.63 47.42,64.21 47.59,64.04 47.59,57.74 46.71,56.86 46.55,56.86 45.64,55.96 45.64,45.48 45.24,45.07 45.24,36.23 60.65,20.82 80.98,20.82 85.14,16.65 85.14,12.82 84.71,12.38 73,12.38 J24.14
SPI6_D1/PRG1_ECAP0_IN_APWM_OUT: length 135.4
  TOP w0.173: J1.36 v1(92.43,101.01)
  L06_SIG2 w0.102: J24.36 52.22,11.17 85.42,11.17 89.64,15.39 89.64,35.55 90.75,36.67 90.75,39.52 91.41,40.18 91.41,53.88 90.02,55.28 90.02,64.61 92.41,67 92.41,72.43 95.1,75.12 95.1,100.5 94.11,101.49 92.91,101.49 v1(92.43,101.01)
TH_EHRPWM0_SYNCI: length 168
  TOP w0.173: U41.34 v1(54.21,126.42)
  L06_SIG2 w0.102: v1(54.21,126.42) 54.21,130.24 59.28,135.32 69.77,135.32 71.81,137.35 95.02,137.35 98.11,134.27 98.11,125.28 96.04,123.2 96.04,112.23 95.48,111.67 95.48,101.61 96.04,101.06 96.04,74.51 93.01,71.49 93.01,58.92 94.08,57.85 94.08,37.76 91.29,34.97 91.29,29.99 v1(90.55,29.25)
  BOTTOM w0.173: J22.1 85.98,27.57 88.87,27.57 v1(90.55,29.25)
TH_EHRPWM0_SYNCO: length 174.9
  TOP w0.173: U41.32 v1(53.21,126.42)
  L06_SIG2 w0.102: v1(90.58,26.81) 91.74,27.98 91.74,34.91 94.31,37.48 94.31,58 93.29,59.02 93.29,71.45 96.27,74.42 96.27,101.26 95.73,101.79 95.73,111.57 96.27,112.11 96.27,123.11 98.34,125.18 98.34,134.36 95.12,137.58 71.42,137.58 69.6,135.75 59.08,135.75 53.21,129.88 v1(53.21,126.42)
  BOTTOM w0.173: J22.3 83.31,26.74 83.77,26.28 90.04,26.28 v1(90.58,26.81)
TH_EHRPWM_TZN_IN0: length 180.6
  TOP w0.173: U41.30 v1(52.21,126.42)
  L06_SIG2 w0.102: v1(52.21,126.42) 52.21,130.4 57.94,136.13 69.37,136.13 71.09,137.86 95.23,137.86 98.62,134.48 98.62,125.06 96.55,122.99 96.55,111.95 96.06,111.47 96.06,101.89 96.55,101.41 96.55,74.3 93.62,71.38 93.62,59.07 94.59,58.1 94.59,37.2 92.18,34.79 92.18,27.32 v1(90.6,25.75)
  BOTTOM w0.173: v1(90.6,25.75) 81.41,25.75 80.77,26.38 J22.5
TH_UART4_CTSN: length 21.1
  TOP w0.173: U42.14 v1(70.97,45.27)
  L06_SIG2 w0.102: J22.15 66.62,29.15 66.62,33.64 68.17,35.19 68.17,42.47 v1(70.97,45.27)
TH_UART4_RTSN: length 11.8
  TOP w0.173: U42.2 v1(70.32,39.67)
  L06_SIG2 w0.102: v1(70.32,39.67) 70.32,38.28 72.54,36.06 72.54,30.85 J22.12
TH_UART4_RXD: length 14.2
  TOP w0.173: U42.5 v1(72.27,39.67)
  L06_SIG2 w0.102: J22.14 70.61,37.3 69.77,38.14 69.77,39.97 70.18,40.38 71.57,40.38 v1(72.27,39.67)
TH_UART4_TXD: length 21.8
  TOP w0.173: U42.11 v1(72.92,45.27)
  L06_SIG2 w0.102: J22.13 69.22,29.1 69.22,31.69 68.86,32.04 68.86,42.31 71.82,45.27 v1(72.92,45.27)
UART3_CTSN: length 176.2
  L03_SIG1 w0.102: v1(64.99,59.75) 66.3,61.05 74.8,61.05 79.9,66.16 84.76,66.16 85.7,67.09 85.7,73.6 85.14,74.16 82.65,74.16 81.76,73.27 71.45,73.27 70.11,74.61 J19.10
  BOTTOM w0.173: U35.6 v1(64.99,59.75) ; J5.15 56.69,184.41 54.36,184.41 45.87,175.92 45.87,139.74 51.21,134.4 51.21,117.07 65.28,103 65.28,90.15 69.07,86.36 69.07,76.74 70.07,75.74 J19.10
UART3_RTSN: length 193.8
  L03_SIG1 w0.102: J19.8 72.11,74.7 73.05,73.75 81.33,73.75 83.63,76.05 85.71,76.05 87.6,74.16 87.6,68.32 84.96,65.67 81.51,65.67 75.52,59.68 70.83,59.68 67.85,56.7 v1(67.19,56.7)
  BOTTOM w0.173: J19.8 71.07,74.7 69.67,74.7 68.63,75.75 68.63,86.24 64.84,90.03 64.84,102.82 50.84,116.82 50.84,133.98 45.44,139.38 45.44,183.45 52.35,190.36 58.78,190.36 59.56,189.58 59.56,187.4 J5.13 ; R226.1 67.02,56.22 67.19,56.4 v1(67.19,56.7)
UART3_RTSN/50MHZ_REFCLK: length 9.2
  BOTTOM w0.173: U35.3 64.97,61.7 64.31,61.03 64.31,56.78 64.86,56.22 R226.2 R225.2
UART3_RX: length 85.5
  TOP w0.173: v1(63.35,139.18) 63.35,142.81 J16.11
  BOTTOM w0.173: J19.4 75.11,76.74 75.11,79.42 71.04,83.48 71.04,90.97 70.52,91.5 U29.37 67.67,91.5 66.01,93.16 66.01,103.06 52.15,116.93 52.15,121.92 55.93,125.7 55.93,127.98 56.72,128.77 56.72,136.11 59.8,139.18 v1(63.35,139.18)
UART3_TX: length 89
  TOP w0.173: R1.1 v1(60.88,138.65)
  BOTTOM w0.173: 72.12,93.51 75.69,97.08 75.69,102.3 74.02,103.98 67.13,103.98 53.39,117.72 53.39,121.58 57.21,125.4 57.21,136.11 59.75,138.65 v1(60.88,138.65) ; 72.12,93.51 74.12,91.51 74.12,85.91 79.37,80.66 79.37,77 J19.2 ; 72.12,93.51 70.78,93.51 70.28,93 U29.40
VPROFI_TRANSA: length 5.1
  BOTTOM w0.254: D4.2 18.98,124.19 T1.8
VPROFI_TRANSB: length 4.8
  BOTTOM w0.254: D5.2 19.71,115.51 T1.5
VSYS_IO_3V3: length 1.4
  BOTTOM w0.254: R166.1 v1(55.08,102.1) ; R159.2 v1(43.14,113.41)
WKUP_I2C0_SCL: length 97.1
  TOP w0.173: J1.65 83.81,113.51 83.51,113.21 83.22,112.92 82.47,112.92 81.96,113.43 81.96,114.03 v1(82.13,114.2)
  L03_SIG1 w0.102: v1(82.13,114.2) 81.96,114.03 81.96,113.35 82.36,112.95 83.42,112.95 83.82,112.55 84.2,112.55 84.26,112.61 91.08,112.61 95.1,108.6 95.1,92.52 90.14,87.57 90.14,76.54 93.17,73.51 93.17,61.42 92.73,60.98 85.93,60.98 83.95,59 79.01,59 77.98,57.98 v1(77.98,50.03)
  BOTTOM w0.173: U36.6 v1(77.98,50.03)
WKUP_I2C0_SDA: length 90.8
  TOP w0.173: J1.63 v1(84.01,113.01)
  L03_SIG1 w0.102: v1(76.71,50.03) 77.17,49.57 78.66,49.57 81.08,51.98 81.08,58.51 81.34,58.78 84.05,58.78 86.02,60.75 93.16,60.75 93.54,61.12 93.54,73.43 95.43,75.33 95.43,110.33 92.91,112.84 84.17,112.84 v1(84.01,113.01)
  BOTTOM w0.173: U36.5 v1(76.71,50.03)
N22955114: length 6.4
  BOTTOM w0.173: R230.1 53,51.43 52.7,51.73 52.7,52.63 C166.2 53.05,52.98 52.76,53.27 52.76,55.52 53.01,55.77 Y4.2
N22955116: length 6.2
  BOTTOM w0.173: R231.1 52,51.43 52.25,51.68 52.25,52.73 C167.2 52.32,53.3 52.32,55.49 52.04,55.77 Y4.1
N23015059: length 3.3
  BOTTOM w0.173: v1(18.08,120.56) 18.06,120.59 D4.1 D5.1
N23015114: length 3.1
  BOTTOM w0.173: U26.10 18.37,103.68 TP5.1
N23022026: length 18.7
  TOP w0.173: v1(51.46,49.32) 49.73,49.32 46.63,46.22 46.63,41.14 v1(47.62,40.15)
  BOTTOM w0.173: U37.13 51.74,49.03 v1(51.46,49.32) ; U37.48 51.74,40.68 51.57,40.5 48.87,40.5 TP17.1 v1(47.62,40.15)
N23027132: length 12.9
  TOP w0.173: J21.A12 6.51,52.46 5.08,53.89 5.08,57.85 7.87,60.64 R66.2
N23035325: length 16.7
  TOP w0.132: 8.49,51.44 9.84,51.44 J21.B12
  TOP w0.173: 8.49,51.44 6.03,51.44 4.19,53.28 4.19,58 6.6,60.42 R65.2
N23036294: length 6.4
  TOP w0.173: Y2.2 37.39,47.51 37.11,47.79 37.11,49.98 37.43,50.3 C46.2 37.08,50.66 37.08,51.55 37.38,51.85 R75.1
N23036296: length 6.2
  TOP w0.173: Y2.1 36.42,47.51 36.68,47.77 36.68,50.01 C45.2 36.63,50.55 36.63,51.6 36.38,51.85 R74.1
N23045041: length 6.4
  BOTTOM w0.173: R184.1 55.92,82.42 55.63,82.72 55.63,83.61 C142.2 55.97,83.97 55.66,84.29 55.66,86.48 55.93,86.76 Y3.2
N23045043: length 6.2
  BOTTOM w0.173: R185.1 54.92,82.42 55.17,82.67 55.17,83.72 C143.2 55.22,84.26 55.22,86.5 54.97,86.76 Y3.1
N23046007: length 13.3
  TOP w0.173: J20.A12 6.61,77.73 5.18,79.16 5.18,83.38 8.26,86.45 R27.2
N23048841: length 17.4
  TOP w0.132: J20.B12 9.84,76.72 8.38,76.72
  TOP w0.173: 8.38,76.72 5.29,76.72 4.52,77.48 4.52,83.61 6.99,86.07 R26.2
N23049007: length 6.4
  TOP w0.173: Y1.2 37.39,78.25 37.14,78.5 37.14,80.74 37.43,81.03 C21.2 37.08,81.39 37.08,82.29 37.38,82.58 R34.1
N23049009: length 6.2
  TOP w0.173: Y1.1 36.42,78.25 36.7,78.53 36.7,80.72 C20.2 36.63,81.29 36.63,82.34 36.38,82.58 R33.1
N23108220: length 19.2
  TOP w0.173: v1(35.84,53.96) 36.12,54.25 U5.13 ; U5.48 36.12,62.6 35.59,63.13 v1(34.01,63.13)
  BOTTOM w0.173: v1(35.84,53.96) 33.35,53.96 30.89,56.43 30.89,62.02 32,63.13 TP14.1 v1(34.01,63.13)
N23109761: length 19.8
  TOP w0.173: v1(50.22,71.13) 49.5,71.85 49.5,78.68 51.13,80.3 v1(54.38,80.3)
  BOTTOM w0.173: v1(50.22,71.13) TP13.1 51.77,71.47 54.46,71.47 54.66,71.67 U30.48 ; U30.13 54.66,80.02 v1(54.38,80.3)
N23111061: length 19.5
  TOP w0.173: U3.13 36.12,84.98 v1(35.84,84.7) ; v1(35.67,93.78) 36.12,93.33 U3.48
  BOTTOM w0.173: v1(35.67,93.78) TP7.1 32.45,93.78 30.84,92.17 30.84,86.22 32.36,84.7 v1(35.84,84.7)
N23254746: length 4.4
  TOP w0.173: R285.2 R286.1 J1.32
N23522908: length 2.2
  BOTTOM w0.173: R157.2 55.89,119.34 U23.15
N23523274: length 2
  BOTTOM w0.173: R221.1 58.76,62.35 U35.15
N23524164: length 1.9
  BOTTOM w0.173: R220.1 71.96,62.47 U34.15
N23737641: length 2.2
  BOTTOM w0.173: R156.2 40.85,119.37 U22.15
N23746928: length 8.3
  TOP w0.173: v1(79.58,112.84) 79.65,112.84 79.66,112.85 81.97,112.85 82.65,112.17 84.05,112.17 84.39,112.51 J1.61
  BOTTOM w0.173: R301.1 R300.1 79.73,112.69 v1(79.58,112.84)
N23748372: length 2.7
  BOTTOM w0.173: R247.1 R248.2 U39.2
N23748397: length 10.2
  BOTTOM w0.173: U39.4 28.09,33.16 29.18,32.07 32,32.07 34.02,30.05 34.02,29.73 35.39,28.36 U40.18
N23749024: length 4.2
  TOP w0.173: R87.2 4.06,35.89 J23.11
N23749026: length 3.7
  TOP w0.173: R103.2 J23.14
N23750460: length 1.4
  BOTTOM w0.173: U28.5 53.45,100.22 R166.2
N23750751: length 1.8
  BOTTOM w0.173: C128.1 53.69,96.14 52.95,96.87 U28.7
N23750795: length 1.4
  BOTTOM w0.173: R159.1 41.51,111.52 U25.5
N23750890: length 1.8
  BOTTOM w0.173: C127.1 62.17,96.14 61.46,96.85 U27.7
N23750996: length 1.8
  BOTTOM w0.173: C117.1 41.62,107.44 41.01,108.05 U25.7
N23770248: length 5.5
  BOTTOM w0.173: U17.2 81.53,152.38 81.7,152.21 81.97,152.21 82.18,152.42 U17.1 82.18,154.76 82.34,154.92 R138.1
N23770260: length 6.5
  BOTTOM w0.173: R138.2 80.44,155.9 80.23,156.11 ; 80.23,156.11 80.11,156 78.78,156 R133.1 ; 80.23,156.11 U17.5
N23770732: length 5.5
  BOTTOM w0.173: U12.2 78.81,160.06 78.98,159.88 79.25,159.88 79.46,160.09 U12.1 79.46,162.43 79.62,162.59 R124.1
N23770754: length 6.5
  BOTTOM w0.173: 77.51,163.78 U12.5 ; 77.51,163.78 77.39,163.67 76.07,163.67 R122.1 ; 77.51,163.78 77.72,163.57 R124.2
N23770913: length 5.5
  BOTTOM w0.173: U18.2 75.28,152.38 75.45,152.21 75.72,152.21 75.93,152.42 U18.1 75.93,154.76 76.09,154.92 R139.1
N23770935: length 6.5
  BOTTOM w0.173: R134.1 72.54,156 73.86,156 73.98,156.11 ; 73.98,156.11 74.19,155.9 R139.2 ; 73.98,156.11 U18.5
N23771115: length 5.5
  BOTTOM w0.173: R125.1 73.22,162.59 73.06,162.43 U13.1 73.06,160.09 72.85,159.88 72.58,159.88 72.41,160.06 U13.2
N23771129: length 6.5
  BOTTOM w0.173: 71.11,163.78 71.32,163.57 R125.2 ; 71.11,163.78 U13.5 ; 71.11,163.78 70.99,163.67 69.66,163.67 R123.1
N23772151: length 5.5
  BOTTOM w0.173: R140.1 69.39,154.92 69.22,154.76 U19.1 69.22,152.42 69.02,152.21 68.75,152.21 68.57,152.38 U19.2
N23772167: length 6.5
  BOTTOM w0.173: 67.27,156.11 U19.5 ; 67.27,156.11 67.16,156 65.83,156 R135.1 ; 67.27,156.11 67.49,155.9 R140.2
N23772825: length 5.5
  BOTTOM w0.173: U14.2 64.31,158.12 64.48,157.95 64.75,157.95 64.96,158.16 U14.1 64.96,160.5 65.12,160.66 R128.1
N23772836: length 6.5
  BOTTOM w0.173: 63.01,161.85 U14.5 ; 63.01,161.85 62.89,161.74 61.56,161.74 R127.1 ; 63.01,161.85 63.22,161.64 R128.2
N23773069: length 5.5
  BOTTOM w0.173: U20.2 57.86,152.38 58.03,152.21 58.3,152.21 58.51,152.42 U20.1 58.51,154.76 58.67,154.92 R141.1
N23773080: length 6.5
  BOTTOM w0.173: R136.1 55.11,156 56.44,156 56.56,156.11 ; 56.56,156.11 56.77,155.9 R141.2 ; 56.56,156.11 U20.5
N23773321: length 5.5
  BOTTOM w0.173: U16.2 87.7,152.38 87.87,152.21 88.14,152.21 88.35,152.42 U16.1 88.35,154.76 88.51,154.92 R137.1
N23773334: length 6.5
  BOTTOM w0.173: R137.2 86.61,155.9 86.4,156.11 ; 86.4,156.11 86.28,156 84.96,156 R132.1 ; 86.4,156.11 U16.5
N23773620: length 4.1
  TOP w0.173: J16.14 R281.1 R280.1
N23773629: length 4.4
  TOP w0.173: R278.1 R279.1 57.63,146.15 J16.16
N23773638: length 4.1
  TOP w0.173: J16.18 R274.1 R275.1
N23842091: length 3.5
  BOTTOM w0.173: R149.2 R148.2 73.59,140.47 J16.3
N23842425: length 3.5
  TOP w0.173: R2.2 R1.2 60.88,142.88 J16.13
N23882322: length 3.7
  TOP w0.173: J2.52 v1(92.43,55.63)
  BOTTOM w0.173: R296.1 J2.52 v1(92.43,55.63)
N23918331: length 3.9
  BOTTOM w0.173: J5.9 R283.2 R284.2
N23924268: length 8.1
  TOP w0.173: FL3.1 C190.1 15.69,19.22 14.42,20.49 J23.2
N23953350: length 2.3
  TOP w0.173: U42.15 R294.2
N23981235: length 2.4
  TOP w0.173: R297.2 U44.15
N24160349: length 2.2
  TOP w0.173: D7.1 23.3,130.19 v1(23.71,129.78)
  BOTTOM w0.173: R362.1 23.85,129.92 v1(23.71,129.78)
N24160363: length 17.1
  L03_SIG1 w0.102: v1(14.99,133.21) 14.11,132.33 14.11,129.72 14.73,129.09 23.94,129.09 v1(24.78,129.93)
  BOTTOM w0.173: R362.2 24.83,129.98 v1(24.78,129.93) ; SW2.2 v1(14.99,133.21)
N24180999: length 10.1
  TOP w0.173: v1(92.28,78.28) 90.29,78.28 89.95,77.93 89.95,75.93 90.24,75.63 J2.112
  BOTTOM w0.173: v1(92.28,78.28) 92.28,79.29 92.89,79.9 92.89,81.01 TP63.1
N24181001: length 13.3
  TOP w0.173: v1(92.37,80.23) 92.27,80.23 91.6,79.57 90.45,79.57 89.29,78.41 89.29,75.93 90.09,75.13 J2.110
  BOTTOM w0.173: v1(92.37,80.23) 92.54,80.4 92.54,83.12 TP62.1
N24208258: length 13
  L03_SIG1 w0.102: v1(14.85,130.11) 21.86,130.11 v1(24.83,133.08)
  BOTTOM w0.173: SW2.1 14.99,130.26 v1(14.85,130.11) ; v1(24.83,133.08) R363.2
N24208263: length 3
  TOP w0.173: D9.1 23.24,133.49 23.56,133.81 v1(24,133.81)
  BOTTOM w0.173: v1(24,133.81) 23.85,133.66 R363.1
N24217026: length 13
  L03_SIG1 w0.102: v1(24.87,141.91) 21.9,138.95 v1(14.89,138.95)
  BOTTOM w0.173: SW3.1 15.03,139.1 v1(14.89,138.95) ; v1(24.87,141.91) R371.2
N24217030: length 3.1
  TOP w0.173: D13.1 23.87,141.88 24.04,142.06 v1(24.04,142.65)
  BOTTOM w0.173: R371.1 23.89,142.49 v1(24.04,142.65)
N24217148: length 2.2
  TOP w0.173: v1(23.75,138.61) 23.34,139.02 D11.1
  BOTTOM w0.173: R370.1 23.89,138.75 v1(23.75,138.61)
N24217172: length 17.4
  L03_SIG1 w0.102: v1(24.82,138.77) 23.51,137.46 15.13,137.46 14.35,138.23 14.35,141.37 v1(15.03,142.05)
  BOTTOM w0.173: v1(24.82,138.77) 24.87,138.82 R370.2 ; SW3.2 v1(15.03,142.05)
N24217959: length 13
  L03_SIG1 w0.102: v1(14.97,147.85) 21.98,147.85 v1(24.95,150.81)
  BOTTOM w0.173: R379.2 v1(24.95,150.81) ; SW4.1 15.11,147.99 v1(14.97,147.85)
N24217963: length 3.1
  TOP w0.173: D17.1 23.35,151.35 23.58,151.57 24.1,151.57 v1(24.12,151.55)
  BOTTOM w0.173: R379.1 23.97,151.39 v1(24.12,151.55)
N24218081: length 2.2
  TOP w0.173: D15.1 23.42,147.92 v1(23.83,147.51)
  BOTTOM w0.173: v1(23.83,147.51) 23.97,147.65 R378.1
N24218105: length 17.3
  L03_SIG1 w0.102: v1(24.9,147.66) 23.64,146.41 15.23,146.41 14.46,147.18 14.46,150.3 v1(15.11,150.94)
  BOTTOM w0.173: R378.2 24.95,147.72 v1(24.9,147.66) ; SW4.2 v1(15.11,150.94)

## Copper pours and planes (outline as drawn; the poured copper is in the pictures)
DGND on L06_SIG2 (solid shape): 41.43,52.19 41.49,52.28 41.59,52.27 41.71,52.22 41.85,52.21 41.93,52.19 41.96,52.11 41.96,32.53 41.9,32.44 41.79,32.46 41.05,33.2 41.05,49.91 41.43,50.29
DGND on L06_SIG2 (solid shape): 67.37,16.47 67.4,16.39 67.36,16.32 67.15,16.13 67,15.9 66.91,15.85 66.82,15.9 66.64,16.16 66.4,16.35 66.39,16.36 66.27,16.48 66.27,16.63 65,17.9 64.97,18.01 65.07,18.07 65.77,18.07
DGND on L06_SIG2 (solid shape): 71.92,39.52 71.93,39.51 72.07,39.35 72.26,39.29 72.3,39.28 72.31,39.24 72.31,37.03 72.25,36.94 72.14,36.96 70.68,38.42 70.68,39.53 70.68,39.54 70.7,39.71 70.65,39.87 70.65,39.97 70.74,40.02 71.42,40.02
DGND on L06_SIG2 (solid shape): 72.31,16.54 72.27,16.46 72.18,16.44 71.49,16.39 71,15.9 70.91,15.85 70.82,15.9 70.54,16.26 70.14,16.45 69.21,16.68 67.48,18.41 67.46,18.52 67.55,18.58 72.31,18.58
DGND on L06_SIG2 (solid shape): 62.31,41.97 62.31,41.6 63.22,40.7 64.02,40.7 64.25,40.94 64.26,40.95 64.29,40.96 64.32,40.97 64.35,40.97 64.38,40.95 64.4,40.93 64.42,40.91 64.42,40.88 64.43,40.87 64.43,40.5 64.02,40.09 62.11,40.09 61.6,39.59 60.96,40.23 60.94,40.24 60.92,40.26 60.89,40.26 60.86,40.26 60.83,40.25 60.81,40.23 60.79,40.2 60.78,40.18 60.78,40.16 60.78,39.32 60.1,39.32 60.03,39.39 60.25,39.6 60.25,40.7 61.97,40.7 61.97,40.64 61.98,40.59 62,40.54 62.03,40.49 62.06,40.44 62.1,40.4 62.15,40.37 62.2,40.35 62.25,40.33 62.31,40.32 62.36,40.32 62.42,40.32 62.47,40.34 62.52,40.36 62.57,40.39 62.61,40.42 62.65,40.46 62.68,40.51 62.7,40.56 62.72,40.62 62.73,40.67 62.73,40.73 62.72,40.78 62.7,40.83 62.68,40.88 62.65,40.93 62.61,40.97 62.57,41.01 62.52,41.04 62.47,41.06 62.42,41.07 62.36,41.08 62.31,41.08 62.25,41.07 62.2,41.05 62.15,41.02 62.1,40.99 62.06,40.95 62.03,40.91 62,40.86 61.98,40.81 61.97,40.75 61.97,40.7 60.25,40.7 60.25,42.66 60.94,43.35
DGND on L06_SIG2 (solid shape): outline of 119 points within 69.22,30.79 72.31,44.92
DGND on L06_SIG2 (solid shape): outline of 201 points within 43.13,19.83 59.06,50.77
DGND on L06_SIG2 (solid shape): 62.91,15.11 63.91,14.47 64.91,15.11 65,15.05 65.2,14.77 65.48,14.57 65.54,14.48 65.48,14.39 65.2,12.77 66.82,13.05 66.91,13.11 67,13.05 67.28,12.7 67.68,12.5 68.6,12.28 68.96,11.92 68.98,11.81 68.89,11.75 57.78,11.75 56.93,12.6 56.93,12.8 57,12.9 57.11,12.87 58.02,12.48 58.82,13.05 58.91,13.11 59.91,12.47 60.91,13.11 61,13.05 62.62,12.77 62.33,14.39 62.28,14.48 62.33,14.57 62.62,14.77 62.82,15.05
DGND on L06_SIG2 (solid shape): outline of 392 points within 40.69,15.85 53.58,28.62
DGND on L06_SIG2 (solid shape): outline of 605 points within 51.21,21.17 72.31,45.37
DGND on TOP: 51.92,46.98 57.23,46.98 57.48,46.73 57.48,42.13 57.23,41.87 51.92,41.87 51.66,42.13 51.66,46.73
DGND on TOP: 1.02,8.02 1.02,31.28 25.63,31.28 25.63,58 25.45,58.17 21.67,58.17 21.49,58.35 21.49,62.09 21.92,62.52 25.25,62.52 25.63,62.9 25.63,69.15 21.84,72.94 21.84,88.15 20.83,89.17 1.14,89.17 1.02,89.3 1.02,196.48 101.19,196.48 101.19,8.02 ; 48 cut-outs
DGND on TOP: 54.84,77.97 60.15,77.97 60.4,77.71 60.4,73.12 60.15,72.86 54.84,72.86 54.58,73.12 54.58,77.71
DGND on TOP: 82.09,42.15 85.7,42.15 85.95,42.41 85.95,44.08 85.7,44.34 82.09,44.34 81.84,44.08 81.84,42.41
DGND on TOP: 82.78,91.3 85.78,91.3 86.03,91.56 86.03,93.44 85.78,93.69 82.78,93.69 82.52,93.44 82.52,91.56
DGND on TOP: 92.89,68.87 99.42,68.87 99.62,69.08 99.62,71.06 99.36,71.31 92.89,71.31 92.63,71.06 92.63,69.13
DGND on TOP: 94.49,88.97 98.91,88.97 99.14,89.19 99.14,93.28 98.83,93.59 94.49,93.59 94.23,93.33 94.23,89.22
DGND on BOTTOM: 36.3,87.04 41.61,87.04 41.86,87.29 41.86,91.89 41.61,92.14 36.3,92.14 36.04,91.89 36.04,87.29
DGND on BOTTOM: 22.94,126.26 22.94,124.98 24.33,124.98 24.33,126.26
DGND on L02_GND1, L04_GND2: 1.02,8.02 1.02,196.48 101.19,196.48 101.19,8.02 ; 34 cut-outs
DGND on L05_PWR1: 1.12,155.46 8.89,155.46 9.4,155.97 9.4,157.75 10.06,158.41 19.43,158.41 19.43,160.16 14.35,160.16 13.9,160.61 13.9,163.74 14.26,164.1 19.43,164.1 19.43,166.38 14.16,166.38 14.16,170.03 14.32,170.19 19.43,170.19 19.43,172.48 15.24,172.48 14.73,172.99 14.73,176.16 14.86,176.29 19.43,176.29 19.43,178.58 13.7,178.58 13.7,181.98 14.1,182.39 19.43,182.39 19.43,184.67 13.97,184.67 13.52,185.12 13.52,188.48 19.43,188.48 19.43,190.77 15.37,190.77 14.99,191.15 14.99,196.45 1.12,196.45
DGND on L06_SIG2: 77.83,11.88 77.83,31.21 77.88,31.23 77.88,32.27 77.86,32.32 77.83,32.36 77.83,46.22 101.19,46.22 101.19,8.19 71.37,8.19 70.89,8.68 70.89,10.58 71.86,11.55 77.5,11.55 ; 7 cut-outs
DGND on L07_GND: 1.02,8.02 1.02,196.48 101.19,196.48 101.19,8.02 ; 34 cut-outs
